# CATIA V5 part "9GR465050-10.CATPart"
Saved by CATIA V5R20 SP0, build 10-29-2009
Part number: 9GR465050-10
Revision: ANY
Definition: UNKNOWN
Nomenclature: 9GR465050-10
Source: Unknown
Bounding box of the stored display mesh (mm): x -24.999 to 24.818, y -45 to 5, z -25 to 25
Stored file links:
  C:\Users\Utente\Desktop\IO LAVORO\3D X SITO CF\CUMSA\3D files GR\GR 465050-10\9GR465050-10.CATPart
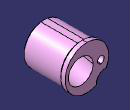
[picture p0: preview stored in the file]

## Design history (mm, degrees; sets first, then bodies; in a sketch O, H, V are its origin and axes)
Body1 "Cortar-Extruir7" (main body)
  Solid1: solid without history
